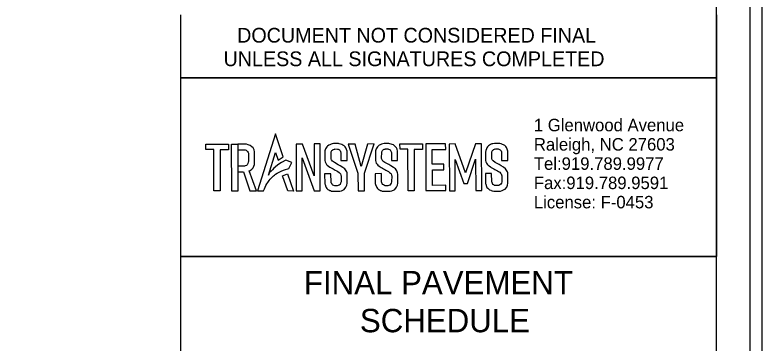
# Model space of a CAD drawing. Extents: x 958711 to 962106, y 831169 to 840840.
# Drawn here: x 960115.9 to 960394.8, y 834433 to 834555.5 of the extents above; entities that cross this region are included whole.
import ezdxf

# ---------------------------------------------------------------- set-up
doc = ezdxf.new("R2010")
doc.units = 0
for name, color, linetype in [('Old_Level_1', 7, 'Continuous'), ('Old_Level_2', 7, 'Continuous'), ('Old_Level_50', 7, 'Continuous'), ('Old_Level_58', 7, 'Continuous'), ('Sheet Plot Border Inside CELL', 7, 'Continuous'), ('Sheet Plot Border Outside CELL', 7, 'Continuous'), ('Sheet Sticker Exception Certification CELL', 7, 'Continuous'), ('Sheet Typical CELL', 7, 'Continuous')]:
    doc.layers.add(name, color=color, linetype=linetype)

msp = doc.modelspace()

# ---------------------------------------------------------------- linework, layer by layer
at = {"layer": 'Old_Level_1'}
for points in [[(960213.1, 834511.13), (960206.44, 834489.79), (960208.66, 834489.8), (960209, 834490.64), (960209.58, 834491.8), (960209.89, 834492.43), (960210.26, 834492.97), (960210.79, 834493.73), (960211.11, 834494.2), (960211.49, 834494.59), (960211.87, 834494.98), (960212.36, 834495.48), (960212.77, 834495.75), (960213.19, 834496.08), (960213.74, 834496.4), (960214.23, 834496.68), (960215.45, 834497.25), (960216.45, 834497.66), (960218.09, 834498.22), (960219.23, 834500.36), (960217.05, 834501.32), (960215.42, 834500.43), (960214.05, 834499.53), (960213.07, 834498.73), (960212.54, 834498.3), (960212.01, 834497.74), (960211.47, 834497.17), (960211.07, 834496.75), (960210.7, 834496.1), (960210.49, 834495.74), (960213.12, 834504.12), (960214.11, 834501.23), (960216.01, 834502.48)], [(960297.57, 834501.19), (960299.88, 834501.2), (960299.88, 834504.67), (960299.69, 834505.38), (960299.4, 834505.97), (960299.11, 834506.36), (960298.74, 834506.71), (960298.3, 834506.99), (960297.87, 834507.17), (960297.87, 834507.17), (960297.41, 834507.36), (960296.93, 834507.48), (960296.61, 834507.56), (960294.86, 834507.53), (960294.33, 834507.43), (960293.87, 834507.36), (960293.41, 834507.12), (960293.01, 834506.91), (960292.61, 834506.62), (960292.3, 834506.31), (960292.06, 834505.94), (960291.87, 834505.55), (960291.61, 834504.85), (960291.56, 834504.34), (960291.56, 834501.17), (960291.68, 834500.69), (960291.91, 834500.2), (960292.19, 834499.79), (960292.49, 834499.48), (960292.94, 834499.13), (960293.39, 834498.78), (960293.68, 834498.56), (960294.16, 834498.34), (960294.65, 834498.11), (960295.04, 834497.86), (960295.48, 834497.57), (960296, 834497.3), (960296.44, 834497.09), (960296.87, 834496.77), (960297.18, 834496.48), (960297.43, 834496.24), (960297.58, 834495.76), (960297.67, 834495.46), (960297.64, 834493.22), (960297.48, 834492.74), (960297.23, 834492.32), (960296.91, 834492.03), (960296.55, 834491.87), (960296.21, 834491.79), (960295.25, 834491.77), (960294.93, 834491.86), (960294.6, 834492.06), (960294.27, 834492.25), (960294.13, 834492.59), (960293.98, 834492.92), (960293.87, 834493.19), (960293.83, 834496.3), (960291.5, 834496.27), (960291.54, 834492.56), (960291.66, 834492.28), (960291.93, 834491.42), (960292.1, 834491.13), (960292.36, 834490.81), (960292.74, 834490.43), (960293.04, 834490.24), (960293.48, 834490.06), (960293.63, 834489.99), (960294.06, 834489.81), (960294.6, 834489.76), (960294.99, 834489.72), (960297.13, 834489.77), (960297.73, 834489.91), (960298.55, 834490.29), (960298.83, 834490.41), (960299.45, 834491.2), (960299.79, 834491.99), (960299.94, 834492.7), (960299.89, 834496.12), (960299.88, 834496.6), (960299.75, 834496.97), (960299.56, 834497.33), (960299.02, 834498.08), (960298.31, 834498.64), (960297.34, 834499.22), (960296.59, 834499.66), (960295.13, 834500.43), (960294.37, 834500.99), (960294.05, 834501.41), (960293.97, 834501.7), (960293.89, 834501.98), (960293.94, 834504.41), (960294.06, 834504.67), (960294.19, 834504.92), (960294.36, 834505.07), (960294.59, 834505.27), (960294.85, 834505.38), (960295.11, 834505.49), (960295.26, 834505.46), (960295.27, 834505.53), (960296.23, 834505.52), (960296.51, 834505.41), (960296.79, 834505.3), (960297.07, 834505.19), (960297.19, 834504.99), (960297.38, 834504.72), (960297.47, 834504.44), (960297.56, 834504.16), (960297.56, 834503.86)], [(960187.14, 834507.28), (960195.61, 834507.29), (960195.61, 834505.21), (960192.5, 834505.21), (960192.51, 834489.79), (960190.16, 834489.78), (960190.15, 834505.31), (960187.18, 834505.31)], [(960196.76, 834507.27), (960199.08, 834507.27), (960199.09, 834489.71), (960196.78, 834489.71)], [(960199.08, 834505.19), (960201.46, 834505.19), (960201.77, 834505.14), (960202.17, 834504.98), (960202.49, 834504.76), (960202.72, 834504.49), (960202.88, 834504.16), (960203, 834503.9), (960203, 834503.32), (960203.01, 834500.83), (960202.95, 834500.5), (960202.87, 834500.05), (960202.74, 834499.76), (960202.54, 834499.5), (960202.27, 834499.29), (960201.84, 834499.14), (960201.52, 834499.09), (960201.19, 834499.05), (960199.08, 834499.04), (960199.09, 834496.93), (960201.2, 834496.94), (960203.57, 834489.78), (960205.99, 834489.81), (960203.34, 834497.35), (960203.72, 834497.48), (960204.25, 834497.88), (960204.74, 834498.41), (960205.09, 834499.05), (960205.3, 834499.68), (960205.29, 834499.87), (960205.33, 834504.43), (960205.13, 834505.18), (960204.76, 834505.85), (960204.35, 834506.33), (960203.65, 834506.8), (960202.98, 834507.03), (960202.3, 834507.25), (960201.89, 834507.25), (960199.08, 834507.27)], [(960220.87, 834507.31), (960220.89, 834489.85), (960223.12, 834489.85), (960223.11, 834502.13), (960227.56, 834489.83), (960229.81, 834489.86), (960229.79, 834507.36), (960227.62, 834507.36), (960227.63, 834495.38), (960223.23, 834507.32)], [(960237.57, 834501.14), (960239.88, 834501.14), (960239.88, 834504.62), (960239.68, 834505.32), (960239.4, 834505.91), (960239.1, 834506.3), (960238.73, 834506.65), (960238.29, 834506.94), (960237.87, 834507.11), (960237.87, 834507.11), (960237.41, 834507.3), (960236.92, 834507.43), (960236.6, 834507.51), (960234.85, 834507.47), (960234.33, 834507.38), (960233.87, 834507.3), (960233.41, 834507.06), (960233, 834506.85), (960232.61, 834506.57), (960232.3, 834506.25), (960232.06, 834505.89), (960231.86, 834505.49), (960231.61, 834504.8), (960231.56, 834504.28), (960231.56, 834501.11), (960231.67, 834500.63), (960231.9, 834500.14), (960232.19, 834499.73), (960232.49, 834499.42), (960232.94, 834499.07), (960233.39, 834498.72), (960233.67, 834498.51), (960234.16, 834498.28), (960234.64, 834498.05), (960235.03, 834497.8), (960235.47, 834497.52), (960236, 834497.25), (960236.43, 834497.03), (960236.86, 834496.71), (960237.17, 834496.42), (960237.42, 834496.18), (960237.58, 834495.7), (960237.67, 834495.4), (960237.63, 834493.17), (960237.47, 834492.68), (960237.23, 834492.26), (960236.9, 834491.97), (960236.55, 834491.81), (960236.2, 834491.74), (960235.24, 834491.72), (960234.92, 834491.81), (960234.59, 834492), (960234.26, 834492.19), (960234.12, 834492.53), (960233.98, 834492.87), (960233.87, 834493.13), (960233.83, 834496.24), (960231.49, 834496.22), (960231.53, 834492.51), (960231.65, 834492.22), (960231.92, 834491.36), (960232.1, 834491.07), (960232.35, 834490.75), (960232.73, 834490.38), (960233.03, 834490.19), (960233.47, 834490), (960233.63, 834489.93), (960234.06, 834489.75), (960234.59, 834489.7), (960234.99, 834489.66), (960237.13, 834489.72), (960237.72, 834489.86), (960238.55, 834490.23), (960238.83, 834490.36), (960239.45, 834491.15), (960239.78, 834491.94), (960239.94, 834492.65), (960239.88, 834496.07), (960239.88, 834496.54), (960239.75, 834496.92), (960239.55, 834497.27), (960239.02, 834498.03), (960238.31, 834498.59), (960237.33, 834499.17), (960236.59, 834499.61), (960235.13, 834500.38), (960234.37, 834500.94), (960234.04, 834501.36), (960233.96, 834501.64), (960233.89, 834501.93), (960233.93, 834504.36), (960234.06, 834504.61), (960234.18, 834504.87), (960234.36, 834505.02), (960234.59, 834505.22), (960234.85, 834505.32), (960235.11, 834505.43), (960235.26, 834505.4), (960235.27, 834505.48), (960236.23, 834505.46), (960236.51, 834505.35), (960236.78, 834505.24), (960237.06, 834505.13), (960237.19, 834504.94), (960237.38, 834504.66), (960237.47, 834504.38), (960237.56, 834504.11), (960237.55, 834503.8)], [(960242.84, 834507.32), (960240.3, 834507.32), (960243.92, 834496.43), (960243.95, 834489.89), (960246.34, 834489.9), (960246.31, 834496.39), (960249.97, 834507.36), (960247.48, 834507.29), (960245.17, 834498.95)], [(960256.44, 834501.16), (960258.75, 834501.16), (960258.75, 834504.64), (960258.55, 834505.34), (960258.27, 834505.93), (960257.97, 834506.32), (960257.6, 834506.67), (960257.16, 834506.96), (960256.74, 834507.13), (960256.74, 834507.13), (960256.28, 834507.32), (960255.8, 834507.44), (960255.48, 834507.52), (960253.73, 834507.49), (960253.2, 834507.4), (960252.74, 834507.32), (960252.28, 834507.08), (960251.88, 834506.87), (960251.48, 834506.58), (960251.17, 834506.27), (960250.93, 834505.9), (960250.73, 834505.51), (960250.48, 834504.81), (960250.43, 834504.3), (960250.43, 834501.13), (960250.54, 834500.65), (960250.77, 834500.16), (960251.06, 834499.75), (960251.36, 834499.44), (960251.81, 834499.09), (960252.26, 834498.74), (960252.55, 834498.52), (960253.03, 834498.3), (960253.51, 834498.07), (960253.9, 834497.82), (960254.34, 834497.53), (960254.87, 834497.27), (960255.31, 834497.05), (960255.74, 834496.73), (960256.04, 834496.44), (960256.3, 834496.2), (960256.45, 834495.72), (960256.54, 834495.42), (960256.51, 834493.18), (960256.35, 834492.7), (960256.1, 834492.28), (960255.77, 834491.99), (960255.42, 834491.83), (960255.08, 834491.76), (960254.12, 834491.74), (960253.79, 834491.83), (960253.46, 834492.02), (960253.14, 834492.21), (960252.99, 834492.55), (960252.85, 834492.88), (960252.74, 834493.15), (960252.7, 834496.26), (960250.36, 834496.23), (960250.41, 834492.53), (960250.52, 834492.24), (960250.8, 834491.38), (960250.97, 834491.09), (960251.22, 834490.77), (960251.6, 834490.39), (960251.91, 834490.2), (960252.34, 834490.02), (960252.5, 834489.95), (960252.93, 834489.77), (960253.47, 834489.72), (960253.86, 834489.68), (960256, 834489.73), (960256.59, 834489.87), (960257.42, 834490.25), (960257.7, 834490.37), (960258.32, 834491.17), (960258.66, 834491.95), (960258.81, 834492.66), (960258.76, 834496.08), (960258.75, 834496.56), (960258.62, 834496.93), (960258.43, 834497.29), (960257.89, 834498.05), (960257.18, 834498.6), (960256.2, 834499.18), (960255.46, 834499.63), (960254, 834500.39), (960253.24, 834500.95), (960252.91, 834501.38), (960252.84, 834501.66), (960252.76, 834501.94), (960252.8, 834504.37), (960252.93, 834504.63), (960253.05, 834504.88), (960253.23, 834505.04), (960253.46, 834505.23), (960253.72, 834505.34), (960253.98, 834505.45), (960254.13, 834505.42), (960254.14, 834505.49), (960255.1, 834505.48), (960255.38, 834505.37), (960255.66, 834505.26), (960255.93, 834505.15), (960256.06, 834504.96), (960256.25, 834504.68), (960256.34, 834504.4), (960256.43, 834504.12), (960256.42, 834503.82)], [(960259.6, 834507.35), (960268.07, 834507.35), (960268.07, 834505.28), (960264.96, 834505.28), (960264.97, 834489.85), (960262.62, 834489.85), (960262.61, 834505.38), (960259.63, 834505.37)], [(960276.67, 834507.35), (960269.28, 834507.34), (960269.3, 834489.92), (960276.77, 834489.92), (960276.77, 834491.9), (960271.73, 834491.89), (960271.72, 834497.73), (960275.94, 834497.74), (960275.93, 834499.81), (960271.68, 834499.81), (960271.68, 834505.31), (960276.69, 834505.31)], [(960284.05, 834496.5), (960280.23, 834507.42), (960278.02, 834507.32), (960278.11, 834489.86), (960280.22, 834489.87), (960280.16, 834501.55), (960283.43, 834492.56), (960284.78, 834492.53), (960287.84, 834501.66), (960287.89, 834489.93), (960290.17, 834489.94), (960290.1, 834507.36), (960287.8, 834507.36)], [(960215.72, 834495.42), (960217.63, 834496.18), (960219.9, 834489.75), (960217.8, 834489.83)]]:
    msp.add_lwpolyline(points, close=True, dxfattribs=at)
at = {"layer": 'Old_Level_50'}
for p, q in [((960177.74, 834465.35), (960377.79, 834465.35)), ((960177.74, 833993.04), (960177.74, 834465.35))]:
    msp.add_line(p, q, dxfattribs=at)
at = {"layer": 'Old_Level_58'}
msp.add_lwpolyline([(960177.75, 834532.04), (960377.8, 834532.04), (960377.8, 834465.35), (960177.75, 834465.35)], close=True, dxfattribs=at)
at = {"layer": 'Sheet Plot Border Inside CELL'}
msp.add_lwpolyline([(960390.3, 834695.64), (958723.8, 834695.64), (958723.8, 833640.54), (960390.3, 833640.54)], close=True, dxfattribs=at)
at = {"layer": 'Sheet Plot Border Outside CELL'}
msp.add_lwpolyline([(960394.8, 834718.09), (958710.8, 834718.09), (958710.8, 833618.09), (960394.8, 833618.09)], close=True, dxfattribs=at)
at = {"layer": 'Sheet Sticker Exception Certification CELL'}
for p, q in [((960177.75, 834532.04), (960177.75, 834555.54)), ((960377.79, 834555.53), (960377.79, 834532.03)), ((960377.79, 834532.04), (960177.75, 834532.04))]:
    msp.add_line(p, q, dxfattribs=at)
at = {"layer": 'Sheet Typical CELL'}
msp.add_lwpolyline([(960377.8, 834693.09), (958877.8, 834693.09), (958877.8, 833643.09), (960377.8, 833643.09)], close=True, dxfattribs=at)

# ---------------------------------------------------------------- texts
at = {"layer": 'Old_Level_2'}
for s, p in [('1 Glenwood Avenue', (960309.6, 834512.08)), ('Raleigh, NC 27603', (960309.6, 834504.88)), ('Tel:919.789.9977 ', (960309.6, 834497.68)), ('Fax:919.789.9591', (960309.6, 834490.49)), ('License: F-0453', (960309.6, 834483.29))]:
    msp.add_text(s, height=4.6576, rotation=360, dxfattribs=at).set_placement(p)
at = {"layer": 'Old_Level_50'}
for s, height, p in [('FINAL PAVEMENT', 8.7206, (960223.74, 834451.19)), ('SCHEDULE', 8.721, (960244.65, 834437.02))]:
    msp.add_text(s, height=height, dxfattribs=at).set_placement(p)
at = {"layer": 'Sheet Sticker Exception Certification CELL'}
for s, p in [('DOCUMENT NOT CONSIDERED FINAL', (960198.82, 834545.2)), ('UNLESS ALL SIGNATURES COMPLETED', (960193.75, 834536.4))]:
    msp.add_text(s, height=5.5, dxfattribs=at).set_placement(p)

doc.saveas('drawing.dxf')
